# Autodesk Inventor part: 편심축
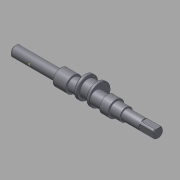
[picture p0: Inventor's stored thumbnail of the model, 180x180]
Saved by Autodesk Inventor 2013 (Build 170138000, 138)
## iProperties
Company: 한국ATC센터
Created: 2015-12
Part Number: 편심축
Document SubType Name: Modeling
Designer: mdu
Density: 7.86 g/cm^3
Mass: 248.518 g
Surface Area: 94.9962 cm^2
Volume: 31.6181 cm^3
Material: 강철, 연강
Author: mdu
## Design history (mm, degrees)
sketch "스케치1"
  geometry: L1 (-84.5, 0)-(84.5, 0); L2 (-84.5, 0)-(-84.5, 6); L3 (-84.5, 6)-(-30.5, 6); L4 (-30.5, 6)-(-30.5, 9.5); L5 (-30.5, 9.5)-(-15.5, 9.5); L6 (-15.5, 9.5)-(-15.5, 7.5); L7 (-15.5, 7.5)-(46.5, 7.5); L8 (84.5, 6)-(84.5, 0); L9 (34.5, 7.5)-(34.5, 9.5); L10 (34.5, 9.5)-(24.5, 9.5); L11 (24.5, 9.5)-(24.5, 7.5); L12 (46.5, 7.5)-(46.5, 6); L13 (46.5, 6)-(84.5, 6); 2 further points
  constraints: 26 end point, 6 parallel, 6 perpendicular, 2 point on line, 1 coincident, 1 horizontal, 1 midpoint
  dimensions: "d1" = 12 diameter of L3 L1; "d2" = 15 diameter of L7 L1; "d4" = 15 distance of L4.end L5.end; "d5" = 19 diameter of L5 L1; "d24" = 10 distance of L9.end L10.end; "d25" = 19 diameter of L10 L1; "d27" = 40 distance between parallel lines of L11 L6; "d28" = 54 distance of L2.end L3.end; "d29" = 50 distance between parallel lines of L8 L9; "d41" = 38 distance between parallel lines of L8 L12; "d42" = 12 diameter of L13 L1
revolve "회전1" stored, may be unused: angle "d6" = 90 deg
node "작업 평면1"
sketch "스케치2"
  geometry: C1 r 7.5 at (0, 0) reference; C2 r 12.5 at (0, 4.5); 1 further point
  constraints: 1 centre point, 1 vertical alignment
  dimensions: "d8" = 4.5 distance of point (0, 0) C2.centre; "d9" = 25 diameter of C2
extrude "돌출1" join sketch "스케치2" distance "d10" = 18; taper "d11" = 0 deg
chamfer "모따기1" distance "d12" = 1; stored, may be unused: second distance "d13" = 2, angle "d14" = 45 deg
chamfer "모따기2" distance "d15" = 0.5; stored, may be unused: second distance "d16" = 2, angle "d17" = 45 deg
node "작업 평면2"
sketch "스케치3"
  geometry: L1 (4, -2)-(18, -2); L2 (18, 2)-(4, 2); L3 (27, 5)-(27, -5) reference; A1 r 2 centre (18, 0) between (18, -2) and (18, 2); A2 r 2 centre (4, 0) between (4, 2) and (4, -2); 2 further points
  constraints: 4 end point, 4 point on circle, 4 tangent, 2 centre point, 1 horizontal, 1 horizontal alignment, 1 midpoint, 1 parallel
  dimensions: "d18" = 7 distance edge to line of A1 L3; "d19" = 4 distance between parallel lines of L2 L1; "d20" = 18 dimension on A1 A2
extrude "돌출2" cut sketch "스케치3" distance "d21" = 2.5; taper "d22" = 0 deg
revolve "회전2" stored, may be unused: angle "d26" = 90 deg
node "작업 평면3"
sketch "스케치10"
  geometry: L1 (-5, -5)-(5, -5); L2 (5, -5)-(5, 5); L3 (5, 5)-(-5, 5); L4 (-5, 5)-(-5, -5); L5 (-5, -5)-(5, 5); L6 (5, -5)-(-5, 5); C1 r 5 at (0, 0) reference; C2 r 6 at (0, 0) reference; A1 r 6 centre (0, 0) between (5, 3.317) and (3.317, 5); A2 r 6 centre (0, 0) between (5, -3.317) and (5, 3.317); A3 r 6 centre (0, 0) between (3.317, -5) and (5, -3.317); A4 r 6 centre (0, 0) between (-3.317, -5) and (3.317, -5); A5 r 6 centre (0, 0) between (-5, -3.317) and (-3.317, -5); A6 r 6 centre (0, 0) between (-5, 3.317) and (-5, -3.317); A7 r 6 centre (0, 0) between (-3.317, 5) and (-5, 3.317); A8 r 6 centre (0, 0) between (3.317, 5) and (-3.317, 5)
  constraints: 16 point on circle, 12 end point, 8 centre point, 8 point on line, 2 midpoint, 2 parallel, 2 tangent, 1 coincident, 1 concentric, 1 horizontal, 1 perpendicular
extrude "돌출4" cut sketch "스케치10" distance "d55" = 17; taper "d56" = 0 deg
sketch "스케치6"
  geometry: L1 (-83.5, -6)-(-30.5, -6) reference; L2 (-84.5, -5)-(-84.5, 5) reference; L3 (-83.5, 6)-(-30.5, 6) reference; L4 (-62.5, 6)-(-62.5, -6); L5 (-62.5, -6)-(-61, -6); L6 (-62.5, -4.5)-(-61, -6); L7 (-62.5, -6)-(-62.5, -4.5); 2 further points
  constraints: 8 end point, 4 point on line, 2 perpendicular, 1 coincident
  dimensions: "d43" = 22 distance between parallel lines of L4 L2; "d44" = 45 deg angle of L6 L7; "d45" = 3 diameter of L5.end L4
revolve "회전3" stored, may be unused: angle "d46" = 90 deg
node "작업점1"
node "작업 평면5"
sketch "스케치11"
  geometry: C1 r 12.5 at (0, 0) reference; C2 r 9.5 at (0, 0); 1 further point
  constraints: 1 centre point
  dimensions: "d57" = 3 radial gap between concentric circles of C1 C2
extrude "돌출5" cut sketch "스케치11" stored distance "d58" = 11; taper "d59" = 0 deg
fillet "모깎기1" dims "d60" = 0.3
chamfer "모따기4" distance "d61" = 0.5; stored, may be unused: second distance "d62" = 2, angle "d63" = 45 deg
node "솔리드1"
node "절단 모서리 투영2"
other parameters: "d7" = 8.5
